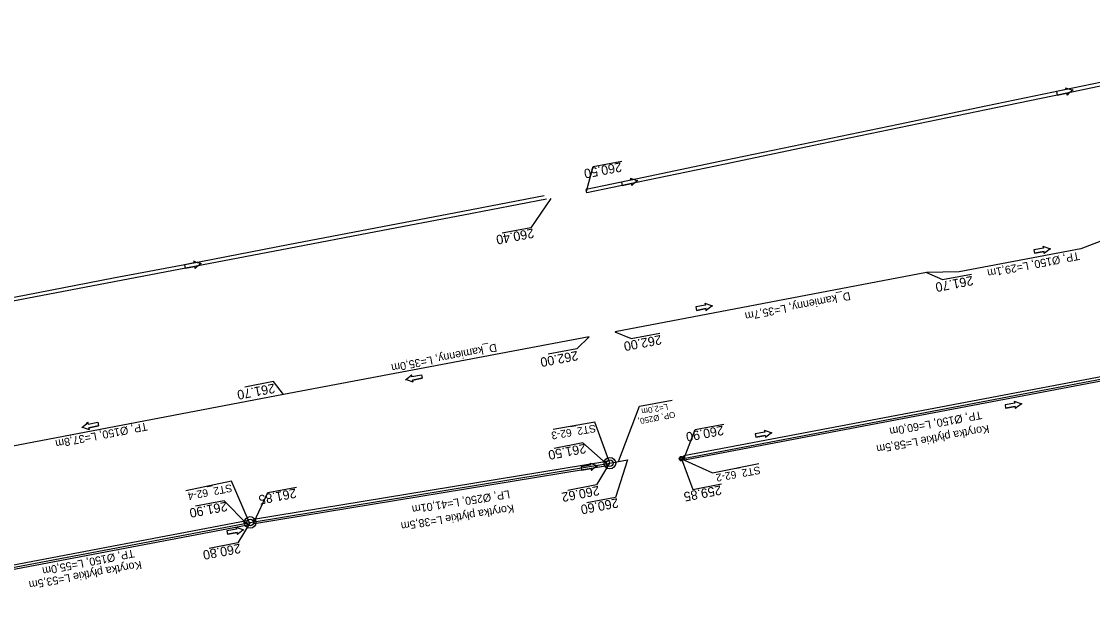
# Model space of a CAD drawing. Extents: x -1 to 65640748, y -22 to 5530284.
# Drawn here: x 6556924.3 to 6557044.8, y 5528563.1 to 5528629.8 of the extents above; entities that cross this region are included whole.
import ezdxf

# ---------------------------------------------------------------- set-up
doc = ezdxf.new("R2010")
doc.units = 0
for name, color, linetype in [('TOR_PROF-studnie i osadniki', 7, 'Continuous'), ('TOR_PS_ODW-drenaze', 7, 'Continuous'), ('TOR_PS_ODW-drenokolektory', 7, 'Continuous'), ('TOR_PS_ODW-kolektory', 7, 'Continuous'), ('TOR_PS_OPIS_O-opisy rurociagow', 7, 'Continuous'), ('TOR_PS_OPIS_O-opisy studni', 7, 'Continuous'), ('TOR_PS_OPIS_T-INFO', 7, 'Continuous'), ('TOR_PS_T-rowy otwarte umocnione', 7, 'Continuous')]:
    doc.layers.add(name, color=color, linetype=linetype)

msp = doc.modelspace()

# ---------------------------------------------------------------- linework, layer by layer
at = {"layer": 'TOR_PROF-studnie i osadniki'}
for centre, radius in [((6556990.53, 5528580.15), 0.65), ((6556998.57, 5528580.65), 0.25), ((6556998.57, 5528580.65), 0.25), ((6556998.57, 5528580.65), 0.125), ((6556998.57, 5528580.65), 0.125), ((6556990.53, 5528580.15), 0.375), ((6556950.06, 5528573.49), 0.65), ((6556950.06, 5528573.49), 0.375)]:
    msp.add_circle(centre, radius, dxfattribs=at)
at = {"layer": 'TOR_PS_ODW-drenaze'}
for p, q in [((6557026.15, 5528601.56), (6556991.11, 5528594.91)), ((6556988.21, 5528594.36), (6556953.82, 5528587.85))]:
    msp.add_line(p, q, dxfattribs=at)
for points in [[(6557054.6, 5528606.95), (6557046.73, 5528605.45), (6557043.51, 5528604.23), (6557029.81, 5528601.64), (6557026.15, 5528601.56)], [(6556998.57, 5528580.65), (6557057.52, 5528591.83)], [(6556953.82, 5528587.85), (6556916.67, 5528580.8), (6556916.67, 5528580.8)], [(6556896.02, 5528563.25), (6556950.06, 5528573.49)]]:
    msp.add_lwpolyline(points, dxfattribs=at)
at = {"layer": 'TOR_PS_ODW-drenokolektory'}
msp.add_lwpolyline([(6556950.06, 5528573.49), (6556990.53, 5528580.15)], dxfattribs=at)
at = {"layer": 'TOR_PS_ODW-kolektory'}
msp.add_line((6556990.53, 5528580.15), (6556992.5, 5528580.54), dxfattribs=at)
msp.add_lwpolyline([(6556990.53, 5528580.15), (6556992.5, 5528580.54)], dxfattribs=at)
at = {"layer": 'TOR_PS_OPIS_O-opisy rurociagow'}
for p, q in [((6557041.84, 5528622.12), (6557040.77, 5528621.9)), ((6557041.84, 5528622.12), (6557040.77, 5528621.9)), ((6557040.77, 5528621.9), (6557040.85, 5528621.51)), ((6557040.77, 5528621.9), (6557040.85, 5528621.51)), ((6557040.85, 5528621.51), (6557041.92, 5528621.73)), ((6557041.92, 5528621.73), (6557040.85, 5528621.51)), ((6556992.89, 5528611.95), (6556991.82, 5528611.73)), ((6556992.89, 5528611.95), (6556991.82, 5528611.73)), ((6556991.82, 5528611.73), (6556991.9, 5528611.34)), ((6556991.82, 5528611.73), (6556991.9, 5528611.34)), ((6556991.9, 5528611.34), (6556992.97, 5528611.56)), ((6556992.97, 5528611.56), (6556991.9, 5528611.34)), ((6557039.29, 5528604.32), (6557038.21, 5528604.13)), ((6557039.29, 5528604.32), (6557038.21, 5528604.13)), ((6557038.21, 5528604.13), (6557038.28, 5528603.73)), ((6557038.21, 5528604.13), (6557038.28, 5528603.73)), ((6557038.28, 5528603.73), (6557039.36, 5528603.92)), ((6557039.36, 5528603.92), (6557038.28, 5528603.73)), ((6556943.76, 5528602.65), (6556942.69, 5528602.44)), ((6556943.76, 5528602.65), (6556942.69, 5528602.44)), ((6556942.69, 5528602.44), (6556942.76, 5528602.05)), ((6556942.69, 5528602.44), (6556942.76, 5528602.05)), ((6556942.76, 5528602.05), (6556943.84, 5528602.26)), ((6556943.84, 5528602.26), (6556942.76, 5528602.05)), ((6557001.27, 5528597.9), (6557000.19, 5528597.71)), ((6557001.27, 5528597.9), (6557000.19, 5528597.71)), ((6557000.19, 5528597.71), (6557000.26, 5528597.32)), ((6557000.19, 5528597.71), (6557000.26, 5528597.32)), ((6557000.26, 5528597.32), (6557001.34, 5528597.51)), ((6557001.34, 5528597.51), (6557000.26, 5528597.32)), ((6556968.25, 5528589.87), (6556969.32, 5528590.09)), ((6556968.25, 5528589.87), (6556969.32, 5528590.09)), ((6556969.4, 5528589.7), (6556968.33, 5528589.48)), ((6556968.33, 5528589.48), (6556969.4, 5528589.7)), ((6556969.32, 5528590.09), (6556969.4, 5528589.7)), ((6556969.32, 5528590.09), (6556969.4, 5528589.7)), ((6557036.06, 5528586.89), (6557034.98, 5528586.71)), ((6557036.06, 5528586.89), (6557034.98, 5528586.71)), ((6557034.98, 5528586.71), (6557035.04, 5528586.32)), ((6557034.98, 5528586.71), (6557035.04, 5528586.32)), ((6557035.04, 5528586.32), (6557036.12, 5528586.5)), ((6557036.12, 5528586.5), (6557035.04, 5528586.32)), ((6556931.85, 5528584.52), (6556932.92, 5528584.74)), ((6556931.85, 5528584.52), (6556932.92, 5528584.74)), ((6556933, 5528584.35), (6556931.93, 5528584.13)), ((6556931.93, 5528584.13), (6556933, 5528584.35)), ((6556932.92, 5528584.74), (6556933, 5528584.35)), ((6556932.92, 5528584.74), (6556933, 5528584.35)), ((6557007.95, 5528583.64), (6557006.88, 5528583.46)), ((6557007.95, 5528583.64), (6557006.88, 5528583.46)), ((6557006.88, 5528583.46), (6557006.94, 5528583.06)), ((6557006.88, 5528583.46), (6557006.94, 5528583.06)), ((6557006.94, 5528583.06), (6557008.02, 5528583.24)), ((6557008.02, 5528583.24), (6557006.94, 5528583.06)), ((6556988.36, 5528579.93), (6556987.28, 5528579.75)), ((6556988.36, 5528579.93), (6556987.28, 5528579.75)), ((6556987.28, 5528579.75), (6556987.35, 5528579.35)), ((6556987.28, 5528579.75), (6556987.35, 5528579.35)), ((6556987.35, 5528579.35), (6556988.43, 5528579.54)), ((6556988.43, 5528579.54), (6556987.35, 5528579.35)), ((6556948.54, 5528572.74), (6556947.46, 5528572.55)), ((6556948.54, 5528572.74), (6556947.46, 5528572.55)), ((6556947.46, 5528572.55), (6556947.53, 5528572.16)), ((6556947.46, 5528572.55), (6556947.53, 5528572.16)), ((6556947.53, 5528572.16), (6556948.6, 5528572.35)), ((6556948.6, 5528572.35), (6556947.53, 5528572.16))]:
    msp.add_line(p, q, dxfattribs=at)
for points in [[(6557041.79, 5528622.34), (6557041.79, 5528622.34)], [(6557041.96, 5528621.51), (6557041.96, 5528621.51)], [(6556992.83, 5528612.17), (6556992.83, 5528612.17)], [(6556993, 5528611.34), (6556993, 5528611.34)], [(6557039.24, 5528604.54), (6557039.24, 5528604.54)], [(6557039.39, 5528603.7), (6557039.39, 5528603.7)], [(6556943.71, 5528602.87), (6556943.71, 5528602.87)], [(6556943.87, 5528602.03), (6556943.87, 5528602.03)], [(6557001.22, 5528598.12), (6557001.22, 5528598.12)], [(6557001.37, 5528597.28), (6557001.37, 5528597.28)], [(6556968.22, 5528590.09), (6556968.22, 5528590.09)], [(6556968.39, 5528589.26), (6556968.39, 5528589.26)], [(6557036.01, 5528587.11), (6557036.01, 5528587.11)], [(6557036.15, 5528586.28), (6557036.15, 5528586.28)], [(6556931.81, 5528584.74), (6556931.81, 5528584.74)], [(6556931.98, 5528583.91), (6556931.98, 5528583.91)], [(6557007.91, 5528583.86), (6557007.91, 5528583.86)], [(6557008.05, 5528583.02), (6557008.05, 5528583.02)], [(6556988.31, 5528580.15), (6556988.31, 5528580.15)], [(6556988.46, 5528579.31), (6556988.46, 5528579.31)], [(6556948.49, 5528572.96), (6556948.49, 5528572.96)], [(6556948.63, 5528572.12), (6556948.63, 5528572.12)]]:
    msp.add_lwpolyline(points, dxfattribs=at)
for centre, radius, start, end in [((6557043.63, 5528626.9), 4.92, 248.0248, 258.4066), ((6557042.24, 5528622.34), 0.458, 180.1393, 208.6006), ((6557043.63, 5528626.9), 4.92, 248.0248, 258.4066), ((6557042.24, 5528622.34), 0.458, 180.1393, 208.6006), ((6557042.38, 5528621.69), 0.458, 174.8687, 203.3299), ((6557042.38, 5528621.69), 0.458, 174.8687, 203.3299), ((6557045.46, 5528618.06), 4.92, 125.0627, 135.4445), ((6557045.46, 5528618.06), 4.92, 125.0627, 135.4445), ((6556994.67, 5528616.73), 4.92, 248.0236, 258.4054), ((6556993.29, 5528612.17), 0.458, 180.1382, 208.5994), ((6556994.67, 5528616.73), 4.92, 248.0236, 258.4054), ((6556993.29, 5528612.17), 0.458, 180.1382, 208.5994), ((6556993.42, 5528611.52), 0.458, 174.8675, 203.3288), ((6556993.42, 5528611.52), 0.458, 174.8675, 203.3288), ((6556996.51, 5528607.89), 4.92, 125.0615, 135.4433), ((6556996.51, 5528607.89), 4.92, 125.0615, 135.4433), ((6557041.23, 5528609.03), 4.92, 246.1449, 256.5268), ((6557039.7, 5528604.52), 0.458, 178.2595, 206.7208), ((6557041.23, 5528609.03), 4.92, 246.1449, 256.5268), ((6557039.7, 5528604.52), 0.458, 178.2595, 206.7208), ((6557039.81, 5528603.87), 0.458, 172.9889, 201.4501), ((6557039.81, 5528603.87), 0.458, 172.9889, 201.4501), ((6557042.78, 5528600.13), 4.92, 123.1828, 133.5647), ((6557042.78, 5528600.13), 4.92, 123.1828, 133.5647), ((6556945.62, 5528607.4), 4.92, 247.1079, 257.4898), ((6556944.17, 5528602.86), 0.458, 179.2225, 207.6838), ((6556945.62, 5528607.4), 4.92, 247.1079, 257.4898), ((6556944.17, 5528602.86), 0.458, 179.2225, 207.6838), ((6556947.32, 5528598.53), 4.92, 124.1458, 134.5277), ((6556947.32, 5528598.53), 4.92, 124.1458, 134.5277), ((6556944.29, 5528602.21), 0.458, 173.9519, 202.4131), ((6556944.29, 5528602.21), 0.458, 173.9519, 202.4131), ((6557003.21, 5528602.62), 4.92, 246.1449, 256.5268), ((6557001.68, 5528598.11), 0.458, 178.2595, 206.7208), ((6557003.21, 5528602.62), 4.92, 246.1449, 256.5268), ((6557001.68, 5528598.11), 0.458, 178.2595, 206.7208), ((6557001.79, 5528597.45), 0.458, 172.9889, 201.4501), ((6557001.79, 5528597.45), 0.458, 172.9889, 201.4501), ((6557004.76, 5528593.72), 4.92, 123.1828, 133.5647), ((6557004.76, 5528593.72), 4.92, 123.1828, 133.5647), ((6556964.72, 5528593.55), 4.92, 304.9397, 315.3215), ((6556964.72, 5528593.55), 4.92, 304.9397, 315.3215), ((6556966.54, 5528584.7), 4.92, 67.9018, 78.2836), ((6556966.54, 5528584.7), 4.92, 67.9018, 78.2836), ((6556967.79, 5528589.91), 0.458, 354.7457, 23.207), ((6556967.79, 5528589.91), 0.458, 354.7457, 23.207), ((6556967.93, 5528589.26), 0.458, 0.0164, 28.4776), ((6556967.93, 5528589.26), 0.458, 0.0164, 28.4776), ((6557038.03, 5528591.6), 4.92, 245.7393, 256.1211), ((6557036.47, 5528587.1), 0.458, 177.8538, 206.3151), ((6557038.03, 5528591.6), 4.92, 245.7393, 256.1211), ((6557036.47, 5528587.1), 0.458, 177.8538, 206.3151), ((6557039.51, 5528582.69), 4.92, 122.7772, 133.159), ((6557039.51, 5528582.69), 4.92, 122.7772, 133.159), ((6557036.57, 5528586.44), 0.458, 172.5832, 201.0444), ((6557036.57, 5528586.44), 0.458, 172.5832, 201.0444), ((6556928.32, 5528588.2), 4.92, 304.9397, 315.3215), ((6556928.32, 5528588.2), 4.92, 304.9397, 315.3215), ((6556931.39, 5528584.56), 0.458, 354.7457, 23.207), ((6556931.39, 5528584.56), 0.458, 354.7457, 23.207), ((6556930.13, 5528579.35), 4.92, 67.9018, 78.2836), ((6556930.13, 5528579.35), 4.92, 67.9018, 78.2836), ((6556931.53, 5528583.91), 0.458, 0.0164, 28.4776), ((6556931.53, 5528583.91), 0.458, 0.0164, 28.4776), ((6557009.93, 5528588.34), 4.92, 245.7383, 256.1202), ((6557008.36, 5528583.84), 0.458, 177.8529, 206.3142), ((6557009.93, 5528588.34), 4.92, 245.7383, 256.1202), ((6557008.36, 5528583.84), 0.458, 177.8529, 206.3142), ((6557008.47, 5528583.18), 0.458, 172.5823, 201.0435), ((6557008.47, 5528583.18), 0.458, 172.5823, 201.0435), ((6557011.41, 5528579.43), 4.92, 122.7762, 133.1581), ((6557011.41, 5528579.43), 4.92, 122.7762, 133.1581), ((6556990.31, 5528584.65), 4.92, 246.0774, 256.4593), ((6556988.77, 5528580.14), 0.458, 178.192, 206.6532), ((6556990.31, 5528584.65), 4.92, 246.0774, 256.4593), ((6556988.77, 5528580.14), 0.458, 178.192, 206.6532), ((6556988.88, 5528579.48), 0.458, 172.9213, 201.3826), ((6556988.88, 5528579.48), 0.458, 172.9213, 201.3826), ((6556991.84, 5528575.75), 4.92, 123.1153, 133.4971), ((6556991.84, 5528575.75), 4.92, 123.1153, 133.4971), ((6556950.48, 5528577.46), 4.92, 246.0764, 256.4583), ((6556948.94, 5528572.95), 0.458, 178.191, 206.6523), ((6556950.48, 5528577.46), 4.92, 246.0764, 256.4583), ((6556948.94, 5528572.95), 0.458, 178.191, 206.6523), ((6556949.06, 5528572.29), 0.458, 172.9204, 201.3816), ((6556949.06, 5528572.29), 0.458, 172.9204, 201.3816), ((6556952.02, 5528568.55), 4.92, 123.1143, 133.4962), ((6556952.02, 5528568.55), 4.92, 123.1143, 133.4962)]:
    msp.add_arc(centre, radius, start, end, dxfattribs=at)
at = {"layer": 'TOR_PS_OPIS_T-INFO'}
for points in [[(6556987.89, 5528610.71), (6556988.65, 5528613.5), (6556991.89, 5528614.1)], [(6556983.87, 5528609.9), (6556981.64, 5528606.61), (6556978.41, 5528605.99)], [(6557026.15, 5528601.56), (6557027.95, 5528600.8), (6557031.19, 5528601.4)], [(6556988.21, 5528594.36), (6556986.81, 5528593), (6556983.57, 5528592.38)], [(6556991.1, 5528594.91), (6556992.91, 5528594.16), (6556996.14, 5528594.76)], [(6556953.82, 5528587.85), (6556952.71, 5528589.33), (6556949.48, 5528588.7)], [(6556991.51, 5528580.34), (6556993.87, 5528586.55), (6556997.53, 5528587.24)], [(6556990.53, 5528580.15), (6556988.84, 5528584.74), (6556984.13, 5528583.94)], [(6556998.87, 5528580.71), (6557000.12, 5528583.92), (6557003.36, 5528584.52)], [(6556990.1, 5528580.1), (6556987.5, 5528582.43), (6556984.27, 5528581.8)], [(6556998.57, 5528580.65), (6556999.87, 5528577.2), (6557003.1, 5528577.81)], [(6556998.57, 5528580.65), (6557002.06, 5528579.06), (6557007.29, 5528580.13)], [(6556990.5, 5528580.16), (6556989.02, 5528577.7), (6556985.78, 5528577.07)], [(6556992.5, 5528580.54), (6556991.16, 5528576.31), (6556987.93, 5528575.69)], [(6556950, 5528573.46), (6556947.96, 5528578.14), (6556942.84, 5528577.06)], [(6556950.5, 5528573.57), (6556952.05, 5528576.85), (6556955.28, 5528577.45)], [(6556949.67, 5528573.38), (6556947.15, 5528575.92), (6556943.92, 5528575.3)], [(6556950.05, 5528573.49), (6556948.67, 5528571.19), (6556945.44, 5528570.57)]]:
    msp.add_lwpolyline(points, dxfattribs=at)
at = {"layer": 'TOR_PS_T-rowy otwarte umocnione'}
for p, q in [((6557057.17, 5528592.02), (6556998.83, 5528580.96)), ((6556990.18, 5528580.34), (6556950.46, 5528573.81)), ((6556949.7, 5528573.68), (6556896.68, 5528563.63))]:
    msp.add_line(p, q, dxfattribs=at)
for points in [[(6557078.89, 5528629.78), (6557071.97, 5528628.39), (6557062.17, 5528626.36), (6557052.38, 5528624.32), (6557042.59, 5528622.29), (6557032.8, 5528620.25), (6557023, 5528618.21), (6557013.21, 5528616.18), (6557003.42, 5528614.14), (6556993.63, 5528612.11), (6556987.85, 5528610.91)], [(6557079.07, 5528629.41), (6557072.04, 5528628), (6557062.25, 5528625.97), (6557052.46, 5528623.93), (6557042.66, 5528621.89), (6557032.87, 5528619.86), (6557023.08, 5528617.82), (6557013.29, 5528615.79), (6557003.49, 5528613.75), (6556993.7, 5528611.71), (6556987.94, 5528610.51), (6556987.85, 5528610.91)], [(6556983.12, 5528610.17), (6556973.97, 5528608.42), (6556964.15, 5528606.54), (6556954.33, 5528604.67), (6556944.5, 5528602.79), (6556934.68, 5528600.92), (6556924.86, 5528599.04), (6556915.04, 5528597.16), (6556905.21, 5528595.29), (6556900.3, 5528594.35), (6556899.32, 5528594.16), (6556896.37, 5528593.6), (6556895.49, 5528593.43), (6556895.39, 5528593.41), (6556890.48, 5528592.47), (6556885.57, 5528591.53), (6556875.75, 5528589.66), (6556865.92, 5528587.78), (6556856.1, 5528585.91)], [(6556983.38, 5528609.81), (6556974.05, 5528608.03), (6556964.22, 5528606.15), (6556954.4, 5528604.27), (6556944.58, 5528602.4), (6556934.76, 5528600.52), (6556924.93, 5528598.65), (6556915.11, 5528596.77), (6556905.29, 5528594.89), (6556900.38, 5528593.96), (6556899.39, 5528593.77), (6556896.45, 5528593.2), (6556895.56, 5528593.04), (6556895.47, 5528593.02), (6556890.55, 5528592.08), (6556885.64, 5528591.14), (6556875.82, 5528589.26), (6556866, 5528587.39), (6556856.18, 5528585.51)], [(6557057.26, 5528591.52), (6556998.92, 5528580.47), (6556998.83, 5528580.96)], [(6556990.26, 5528579.85), (6556950.55, 5528573.32), (6556950.46, 5528573.81)], [(6556949.8, 5528573.19), (6556896.78, 5528563.14), (6556896.69, 5528563.63)]]:
    msp.add_lwpolyline(points, dxfattribs=at)

# ---------------------------------------------------------------- texts
at = {"layer": 'TOR_PS_OPIS_O-opisy rurociagow'}
for s, height, rotation, p in [('TP, Ø150, L=29,1m', 0.9, 190.9157, (6557043.26, 5528603.89)), ('D_kamienny, L=35,7m', 0.9, 191.128, (6557017.5, 5528599.39)), ('D_kamienny, L=35,0m', 0.9, 191.128, (6556977.72, 5528593.59)), ('L=2,0m', 0.675, 190.821, (6556997, 5528586.83)), ('OP, Ø250, ', 0.675, 190.821, (6556997.81, 5528585.95)), ('TP, Ø150, L=60,0m', 0.9, 190.3457, (6557032.28, 5528586.01)), ('TP, Ø150, L=37,8m', 0.9, 190.9157, (6556938.43, 5528584.73)), ('Korytka płytkie L=58,5m', 0.9, 190.3457, (6557033.11, 5528584.46)), ('LP, Ø250, L=41,01m', 0.9, 189.0561, (6556979.2, 5528577.12)), ('Korytka płytkie L=38,5m', 0.9, 189.0561, (6556979.68, 5528575.51)), ('TP, Ø150, L=55,0m', 0.9, 191.184, (6556936.95, 5528570.47)), ('Korytka płytkie L=53,5m', 0.9, 190.3457, (6556937.78, 5528569.18))]:
    msp.add_text(s, height=height, rotation=rotation, dxfattribs=at).set_placement(p)
at = {"layer": 'TOR_PS_OPIS_O-opisy studni'}
for s, height, rotation, p in [('ST2_62-3', 0.862, 189.696, (6556988.87, 5528584.5)), ('ST2_62-2', 0.862, 190.2999, (6557007.38, 5528579.81)), ('ST2_62-4', 0.863, 191.029, (6556947.95, 5528577.8))]:
    msp.add_text(s, height=height, rotation=rotation, dxfattribs=at).set_placement(p)
at = {"layer": 'TOR_PS_OPIS_T-INFO'}
for s, rotation, p in [('260.50', 190.7506, (6556991.76, 5528613.96)), ('260.40', 190.7159, (6556981.88, 5528606.53)), ('261.70', 190.7506, (6557031.29, 5528601.2)), ('262.00', 190.7506, (6556996.24, 5528594.56)), ('262.00', 190.7159, (6556986.85, 5528592.77)), ('261.70', 190.7159, (6556952.75, 5528589.1)), ('260.90', 190.7506, (6557003.23, 5528584.38)), ('261.50', 190.7159, (6556987.74, 5528582.34)), ('261.85', 190.7506, (6556955.16, 5528577.31)), ('260.62', 190.7159, (6556989.25, 5528577.61)), ('259.85', 190.7506, (6557002.98, 5528577.66)), ('261.90', 190.7159, (6556947.39, 5528575.83)), ('260.60', 190.7159, (6556991.39, 5528576.22)), ('260.80', 190.7159, (6556948.9, 5528571.11))]:
    msp.add_text(s, height=1.05, rotation=rotation, dxfattribs=at).set_placement(p)

doc.saveas('drawing.dxf')
